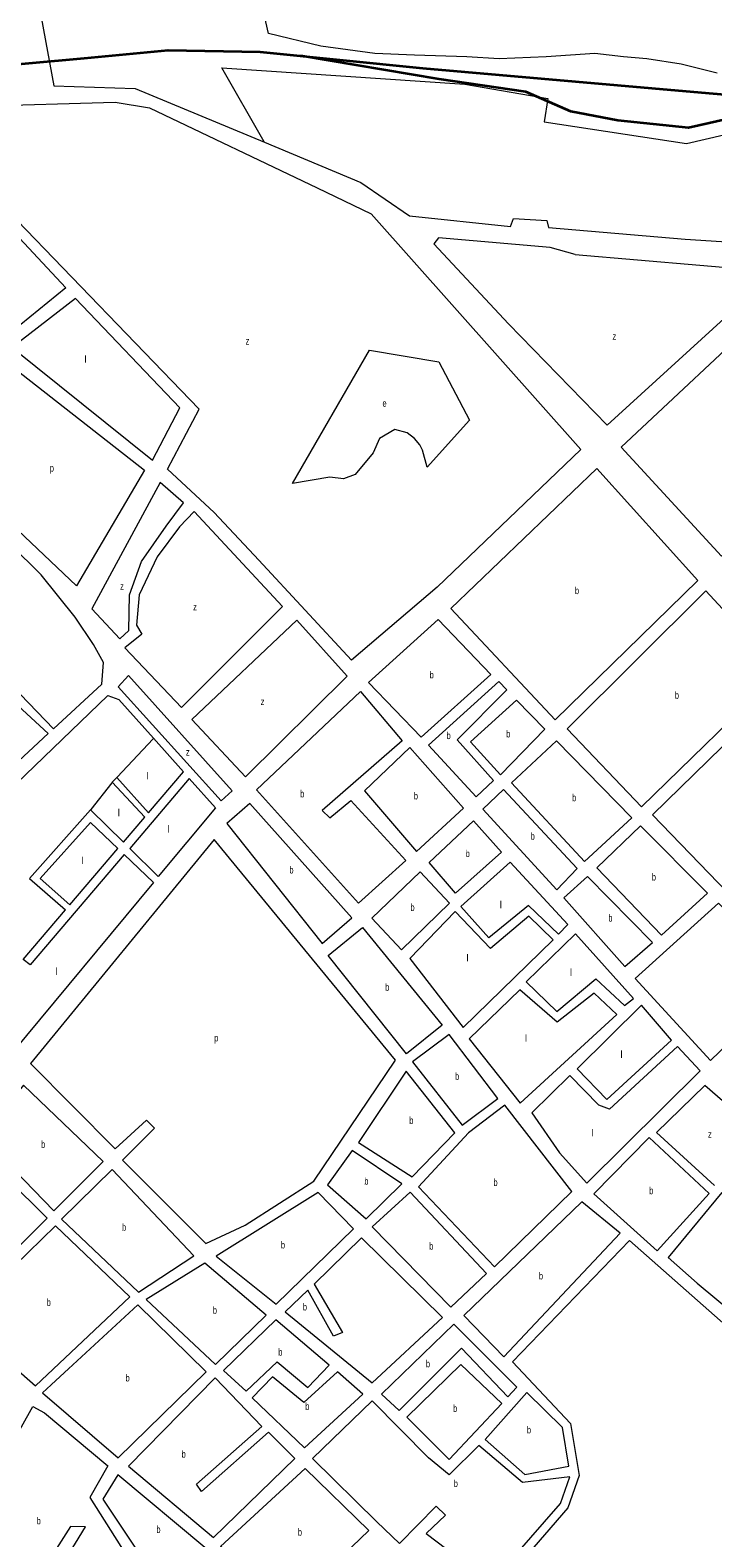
# Model space of a CAD drawing. Extents: x 639657 to 671642, y 222838 to 252123.
# Drawn here: x 657088 to 658048, y 236660 to 238779 of the extents above; entities that cross this region are included whole.
import ezdxf

# ---------------------------------------------------------------- set-up
doc = ezdxf.new("R2010")
doc.units = 0
doc.header["$LTSCALE"] = 4
for name, color, linetype, lineweight in [('1', 7, 'Continuous', 13), ('21', 7, 'Continuous', 13), ('57', 7, 'Continuous', 35)]:
    doc.layers.add(name, color=color, linetype=linetype, lineweight=lineweight)
doc.layers.add('7', color=7, linetype='Continuous')

msp = doc.modelspace()

# ---------------------------------------------------------------- linework, layer by layer
at = {"layer": '1'}
for p, q in [((657655.57, 238478.5), (657760.45, 238366.11)), ((657254.552, 237678.856), (657303.742, 237736.423)), ((657312.059, 237727.134), (657228.215, 237628.849)), ((657219.322, 237637.626), (657249.293, 237672.701)), ((657143.911, 237549.37), (657211.652, 237628.649)), ((657220.682, 237620.018), (657261.621, 237580.884)), ((657268.461, 237589.126), (657228.215, 237628.849)), ((657261.621, 237580.884), (657062.55, 237340.95))]:
    msp.add_line(p, q, dxfattribs=at)
for points in [[(657101.809, 238804.075), (657103.74, 238796.77), (657121.47, 238700.15), (657236.02, 238696.55), (657417.718, 238621.02)], [(657346.85, 238100.67), (657281.57, 238161.75), (657325.92, 238246.14), (657057.44, 238524.44), (657009.16, 238564.62), (656883.5, 238604.51), (656915.48, 238637), (657012.81, 238671.73), (657207.85, 238677.53), (657255.88, 238669.58), (657491.87, 238557.2)], [(657417.718, 238621.02), (657553.13, 238564.73), (657621.48, 238517.53), (657763.17, 238502.79), (657767.72, 238514.18), (657814.55, 238511.05), (657816.94, 238501.44), (658008.65, 238484.71), (658234.16, 238470.44), (658437.85, 238447.56), (658803.79, 238404.54), (658836.212, 238506.095), (658847.523, 238541.526)], [(657491.87, 238557.2), (657567.48, 238520.39), (657862.11, 238189.15)], [(657854.22, 238463.53), (657819.04, 238473.4), (657662.35, 238486.73), (657655.57, 238478.5)], [(657854.22, 238463.53), (658117, 238441), (658116.4, 238421.64), (657899.41, 238223.39), (657760.45, 238366.11)], [(657862.11, 238189.15), (657660.56, 237996.12), (657540.07, 237893.2)], [(657540.07, 237893.2), (657409.76, 238033.98), (657346.85, 238100.67)], [(656861.16, 237921.85), (656938.73, 237950.89), (657113.57, 237790.34), (656892.805, 237584.758)], [(657002.425, 237386.535), (656954.73, 237411.212), (656943.61, 237413.2), (656897.56, 237449.66), (656877.49, 237457.22), (656810.54, 237475.52), (656914.39, 237571.5), (657197.7, 237843.44), (657212.88, 237837.91), (657261.618, 237783.473), (657303.742, 237736.423)], [(657254.552, 237678.856), (657210.06, 237728.616), (657203.731, 237721.648), (657249.293, 237672.701)], [(657312.059, 237727.134), (657348.86, 237686.03), (657268.461, 237589.126)], [(657219.322, 237637.626), (657173.344, 237683.006), (657087.252, 237586.716), (657138.079, 237542.545)], [(657143.911, 237549.37), (657102.444, 237586.716), (657173.344, 237665.268), (657211.652, 237628.649)], [(657220.682, 237620.018), (657088.518, 237465.087), (657078.389, 237472.689), (657138.079, 237542.545)], [(658114.782, 237227.812), (658036.71, 237295.41), (657968.51, 237229.77), (658049.867, 237154.898)], [(658060.47, 237145.14), (657984.74, 237053.96), (658025.9, 237017.99), (658078.08, 236974.09), (658233.33, 237125.17), (658124.091, 237219.753)], [(658329.867, 236317.332), (658539.21, 236592.55), (658536.53, 236612.24), (658065.97, 236958.54), (657930.86, 237077.69), (657766.4, 236907.11), (657847.52, 236820.47), (657860.07, 236747.72), (657844.01, 236702.2), (657778.2, 236626.44), (657749.87, 236598.88), (657718.73, 236598.11), (657605.75, 236462.78)]]:
    msp.add_lwpolyline(points, dxfattribs=at)
for points in [[(657049.77, 238344.27), (656818.02, 238522.27), (656872.13, 238593.47), (657003.17, 238553.21), (657047.39, 238514.26), (657138.73, 238416.48)], [(658059.81, 238039.29), (658433.73, 238409.6), (658160.09, 238436.69), (658160.66, 238413.6), (658171.73, 238400.98), (658165.04, 238388.99), (658131.13, 238391.38), (657918.98, 238192.71)], [(657063.28, 238332.77), (657260.12, 238174.29), (657298.86, 238247.69), (657152.26, 238401.56)], [(657249.24, 238160.2), (657153.55, 237997.59), (656924.85, 238214.24), (657046.11, 238318.92)], [(658026.8, 238005.16), (657884.79, 238162.85), (657679.58, 237965.96), (657826.4, 237809.47)], [(657303.74, 238114.4), (657271.11, 238142.86), (657175.04, 237965.32), (657214.23, 237923.3), (657226.84, 237934.9), (657227.75, 237984.89), (657244.85, 238032.06), (657279.61, 238081.81)], [(657443.08, 237968.72), (657318.87, 238102.13), (657298.45, 238080.67), (657266.72, 238038.51), (657241.71, 237985.23), (657237.93, 237942.69), (657245.23, 237929.98), (657221.53, 237910.59), (657301, 237826.58)], [(657177.35, 237915.41), (657151.56, 237953.84), (657103.73, 238013.01), (657060.74, 238056), (656959.43, 237955.38), (657063.11, 237857.11), (657121.19, 237796.89), (657188.94, 237859.81), (657191.42, 237889.96)], [(658142.82, 237877.46), (657947.65, 237687.27), (657842.83, 237796.98), (658037.9, 237990.93)], [(657462.91, 237949.32), (657315.39, 237809.74), (657391, 237729.4), (657533.64, 237871.01)], [(657735.62, 237873.31), (657661.7, 237950.47), (657563.95, 237862.09), (657637.87, 237784.93)], [(657212.089, 237855.738), (657356.925, 237695.675), (657372.118, 237709.612), (657226.519, 237871.784)], [(657758.18, 237851.84), (657747.15, 237863.39), (657648.35, 237773.91), (657715.17, 237701.41), (657739.33, 237724.03), (657688.34, 237781.3)], [(658174.22, 237456.98), (658354.87, 237647.36), (658158.13, 237866.56), (657962.98, 237675.83)], [(657552.44, 237849.45), (657611.12, 237779.97), (657498.57, 237682.09), (657509.57, 237671.61), (657539.06, 237695.98), (657616.37, 237611.92), (657549.63, 237551.71), (657406.5, 237710.98)], [(657811.69, 237796.21), (657771.98, 237837.14), (657707.34, 237778.59), (657749.33, 237732.34)], [(657867.43, 237610.42), (657934.06, 237671.89), (657827.86, 237779.77), (657764.66, 237720.9)], [(657697.3, 237685.38), (657622.1, 237770.57), (657558.06, 237709.88), (657631.1, 237624.64)], [(657828.58, 237570.42), (657724.74, 237683.91), (657753.61, 237711.49), (657857.23, 237600.73)], [(657540.47, 237531.06), (657397.3, 237691.94), (657364.69, 237663.74), (657498.91, 237495.11)], [(657750.96, 237623.31), (657686.3, 237565.83), (657649.22, 237608.97), (657711.18, 237667.46)], [(657975.78, 237506.89), (658040.06, 237565.95), (657946.17, 237660.37), (657884.5, 237601.3)], [(657218.37, 237190.65), (657335.21, 237073.75), (657390.44, 237099.31), (657487.21, 237161.36), (657601.69, 237331.3), (657346.76, 237641.39), (657088.7, 237326.56), (657207.76, 237206.5), (657251.88, 237246.82), (657262.91, 237235.81)], [(657763.12, 237609.64), (657843.75, 237521.9), (657830.66, 237508.14), (657788.82, 237548.48), (657732.99, 237503.04), (657693.75, 237547.21)], [(657677.52, 237551.64), (657636.66, 237595.77), (657568.42, 237530.68), (657610.37, 237486.04)], [(657924.22, 237462.63), (657962.8, 237496.38), (657871.59, 237589.32), (657838.52, 237559.38)], [(658044.63, 237330.74), (658160.6, 237442.68), (658055.8, 237551.85), (657938.6, 237445.79)], [(657696.9, 237376.96), (657823.33, 237500.44), (657789.2, 237533.44), (657735.52, 237488.06), (657685.86, 237540.03), (657621.95, 237473.97)], [(657555.31, 237517.46), (657667.26, 237380.52), (657617.22, 237340.06), (657507.39, 237478.13)], [(657936.08, 237417.79), (657854.83, 237508.74), (657785.57, 237441.47), (657828.52, 237399.55), (657883.27, 237445.5), (657923.43, 237407.8)], [(657912.99, 237395.19), (657881.07, 237425.56), (657828.9, 237384.51), (657776.72, 237429.97), (657705.36, 237361.05), (657776.91, 237270.93)], [(657989.65, 237359.47), (657947.59, 237408.4), (657856.85, 237319.12), (657898.76, 237276.09)], [(657745.59, 237277.14), (657677.26, 237367.34), (657625.55, 237328.98), (657695.47, 237239.9)], [(658029.94, 237316.41), (657997.93, 237350.54), (657902.33, 237262.21), (657887.68, 237267.76), (657846.88, 237309.73), (657793.37, 237257.37), (657832.44, 237201.02), (657870.52, 237158.26)], [(657625.27, 237167.25), (657685, 237228.9), (657616.74, 237315.87), (657549.92, 237215.36)], [(657191.01, 237188.89), (657079.25, 237296.24), (657061.01, 237273.76), (657050.58, 237282.63), (657009.87, 237234.87), (657121.83, 237119.47)], [(657849.7, 237146.76), (657755.33, 237267.97), (657704.19, 237229.09), (657634.09, 237153.2), (657741.14, 237040.9)], [(657059.95, 237056.87), (657112.36, 237109.21), (656998.9, 237221.33), (656871.59, 237070.98), (656946.35, 237003.01), (657007.32, 237035.15)], [(657958.48, 237222.54), (658042.503, 237143.91), (657969.46, 237063.25), (657880.42, 237143.23)], [(657506.15, 237155.92), (657560.53, 237108.39), (657610.88, 237157.46), (657540.94, 237204.07)], [(657318.46, 237056.14), (657203.66, 237177.39), (657132.33, 237107.91), (657240.75, 237005.32)], [(657542.63, 237093.97), (657493.02, 237145.14), (657349.63, 237055.85), (657434.07, 236988.11)], [(657729.56, 237031.48), (657622.45, 237145.93), (657568.89, 237096.77), (657679.71, 236984.03)], [(657753.87, 236914.32), (657917.71, 237088.11), (657863.44, 237131.9), (657697.62, 236972.56)], [(657228.47, 236998.76), (657123.92, 237098.21), (656989.15, 236967.02), (657095.7, 236873.52)], [(657667.71, 236969.76), (657554.23, 237081.37), (657487.62, 237016.31), (657527.47, 236948.53), (657514.71, 236943.38), (657478.7, 237008.03), (657446.69, 236977.68), (657569.01, 236877.58)], [(657419.95, 236972.71), (657333.76, 237045.78), (657251.22, 236994.83), (657348.61, 236903.78)], [(657335.85, 236893.47), (657239.5, 236987.22), (657105.62, 236863.56), (657212.12, 236772.21)], [(657508.59, 236902.6), (657433.41, 236966.26), (657359.98, 236895.14), (657391.87, 236865.85), (657435.42, 236907.23), (657478.76, 236871.24)], [(657759.62, 236858.02), (657772.47, 236871.76), (657683.96, 236960.4), (657582.18, 236861.74), (657606.85, 236838.88), (657694.65, 236926.42)], [(657555.81, 236861.88), (657520.11, 236893.22), (657472.84, 236850.14), (657428.97, 236886.12), (657400.16, 236856.93), (657473.91, 236786.25)], [(657617.84, 236829.38), (657677.4, 236770.07), (657751.04, 236848.85), (657693.8, 236903.73)], [(657414.06, 236816.45), (657348.43, 236884.65), (657226.37, 236760.75), (657345.98, 236660.6), (657460.31, 236771.41), (657423.39, 236808.63), (657329.32, 236725.18), (657322.09, 236735.2)], [(657645.03, 236665.92), (657718.43, 236610.11), (657744.87, 236610.76), (657769.405, 236634.627), (657833.45, 236708.34), (657846.67, 236745.83), (657780.27, 236737.69), (657718.84, 236789.54), (657677.19, 236748.54), (657648.3, 236772.33), (657568.94, 236852.54), (657485.02, 236771.49), (657575.35, 236682.42), (657607.57, 236652.19), (657658.84, 236704.58), (657672.06, 236692.04)], [(657845.53, 236760.56), (657836.3, 236814.89), (657786.34, 236864.37), (657727.8, 236798.34), (657783.51, 236749.17)], [(656991.86, 236665.75), (657092.13, 236844.43), (657108.46, 236835.7), (657197.35, 236761.1), (657172.15, 236716.43), (657264.99, 236569.95), (657211.62, 236513.3), (657109.94, 236583.82), (657166.19, 236675.46), (657145.23, 236676.01), (657093.55, 236594.69)], [(657333.98, 236646.33), (657211.64, 236748.57), (657190.47, 236714.2), (657276.8, 236585.03)], [(657458.4, 236568.86), (657355.97, 236647.95), (657474.63, 236757.26), (657564.37, 236670.33)]]:
    msp.add_lwpolyline(points, close=True, dxfattribs=at)
at = {"layer": '21'}
for points in [[(658053.9, 238718.116), (658003.257, 238730.786), (657955.146, 238738.387), (657922.228, 238740.921), (657881.714, 238745.989), (657813.346, 238740.921), (657747.51, 238738.387), (657701.931, 238740.921), (657628.499, 238743.455), (657572.792, 238745.989), (657496.827, 238756.125), (657423.395, 238773.863), (657413.267, 238816.94)], [(657417.718, 238621.02), (657417.431, 238621.519), (657357.559, 238725.718), (657699.399, 238702.912), (657815.878, 238682.641), (657810.814, 238649.7), (658010.853, 238619.292), (658109.607, 238642.098), (658117.203, 238669.971), (658835.712, 238506.209), (658836.212, 238506.095)], [(657210.06, 237728.616), (657210.53, 237729.116), (657261.148, 237782.973), (657261.618, 237783.473)], [(657203.731, 237721.648), (657203.338, 237721.148), (657173.737, 237683.506), (657173.344, 237683.006)]]:
    msp.add_lwpolyline(points, dxfattribs=at)
msp.add_lwpolyline([(657456.926, 238141.749), (657565.196, 238329.159), (657662.684, 238312.688), (657705.73, 238230.335), (657646.225, 238164.453), (657639.894, 238188.525), (657636.096, 238196.127), (657628.5, 238204.996), (657618.371, 238212.598), (657600.646, 238217.665), (657579.123, 238204.996), (657570.26, 238184.724), (657544.939, 238154.317), (657528.48, 238147.982), (657509.489, 238150.516)], close=True, dxfattribs=at)
at = {"layer": '57'}
for points in [[(654002.119, 239034.206), (654070.566, 238864.887), (654144.193, 238697.237), (654202.587, 238585.471), (654273.675, 238478.785), (654332.069, 238397.5), (654423.469, 238313.675), (654563.107, 238227.31), (654677.356, 238184.128), (654752.252, 238182.858), (655194.015, 238248.902), (655762.722, 238406.391), (656798.58, 238678.186), (656935.679, 238718.829), (657164.177, 238739.15), (657282.235, 238750.582), (657411.717, 238748.041), (657640.216, 238725.18), (658021.046, 238692.158), (658135.295, 238681.998), (658828.406, 238524.508), (660845.547, 238106.667)], [(658446.306, 238980.466), (658455.192, 238900.451), (658460.27, 238844.568), (658460.27, 238793.765), (658445.036, 238735.341), (658399.337, 238689.619), (658325.71, 238669.298), (658249.543, 238676.918), (658175.916, 238687.079), (658117.522, 238681.998), (658081.978, 238656.597), (658013.429, 238641.356), (657914.413, 238651.517), (657848.402, 238664.217), (657784.93, 238692.159), (657663.065, 238709.94), (657468.858, 238742.324)]]:
    msp.add_lwpolyline(points, dxfattribs=at)

# ---------------------------------------------------------------- texts
at = {"layer": '7'}
for s, width, p in [('z', 0.8, (657906.667, 238343.46)), ('z', 0.8, (657391.043, 238336.825)), ('e', 0.75, (657583.486, 238249.405)), ('p', 0.75, (657116.022, 238158.255)), ('z', 0.8, (657214.775, 237992.282)), ('b', 0.75, (657853.988, 237986.16)), ('z', 0.8, (657317.327, 237963.142)), ('b', 0.75, (657649.785, 237867.7)), ('b', 0.75, (657994.324, 237839.1)), ('z', 0.8, (657412.283, 237830.11)), ('b', 0.75, (657673.577, 237782.4)), ('b', 0.75, (657757.31, 237784.74)), ('z', 0.8, (657307.199, 237759.16)), ('b', 0.75, (657467.839, 237700.58)), ('b', 0.75, (657627.543, 237697.605)), ('b', 0.75, (657849.94, 237695.095)), ('b', 0.75, (657791.82, 237640.955)), ('b', 0.75, (657700.406, 237616.645)), ('b', 0.75, (657452.729, 237593.525)), ('b', 0.75, (657962.032, 237583.63)), ('b', 0.75, (657622.836, 237540.905)), ('b', 0.75, (657900.933, 237525.975)), ('b', 0.75, (657587.243, 237428.76)), ('p', 0.75, (657347.106, 237357.57)), ('b', 0.75, (657685.493, 237303.62)), ('b', 0.75, (657621.201, 237241.56)), ('z', 0.8, (658040.826, 237222.109)), ('b', 0.75, (657103.673, 237207.855)), ('b', 0.75, (657557.996, 237156.23)), ('b', 0.75, (657739.478, 237154.435)), ('b', 0.75, (657958.351, 237142.895)), ('b', 0.75, (657217.472, 237091.355)), ('b', 0.75, (657440.761, 237066.625)), ('b', 0.75, (657649.174, 237064.98)), ('b', 0.75, (657803.329, 237023.11)), ('b', 0.75, (657111.654, 236985.865)), ('b', 0.75, (657345.087, 236974.78)), ('b', 0.75, (657471.594, 236979.475)), ('b', 0.75, (657437.137, 236916.055)), ('b', 0.75, (657644.535, 236899.64)), ('b', 0.75, (657222.462, 236879.715)), ('b', 0.75, (657474.965, 236839.735)), ('b', 0.75, (657682.696, 236836.9)), ('b', 0.75, (657786.477, 236806.77)), ('b', 0.75, (657301.261, 236772.625)), ('b', 0.75, (657683.654, 236731.325)), ('b', 0.75, (657097.589, 236678.865)), ('b', 0.75, (657265.818, 236666.8)), ('b', 0.75, (657464.575, 236663.06))]:
    msp.add_text(s, height=10, dxfattribs=dict(at, width=width)).set_placement(p)
for p in [(657164.551, 238311.181), (657251.91, 237725.842), (657211.396, 237673.896), (657281.03, 237651.091), (657160.753, 237606.747), (657748.212, 237544.665), (657124.037, 237450.91), (657701.367, 237469.914), (657846.966, 237449.643), (657783.662, 237357.154), (657917.866, 237334.348), (657877.352, 237224.122)]:
    msp.add_text('l', height=10, dxfattribs=at).set_placement(p)

doc.saveas('drawing.dxf')
